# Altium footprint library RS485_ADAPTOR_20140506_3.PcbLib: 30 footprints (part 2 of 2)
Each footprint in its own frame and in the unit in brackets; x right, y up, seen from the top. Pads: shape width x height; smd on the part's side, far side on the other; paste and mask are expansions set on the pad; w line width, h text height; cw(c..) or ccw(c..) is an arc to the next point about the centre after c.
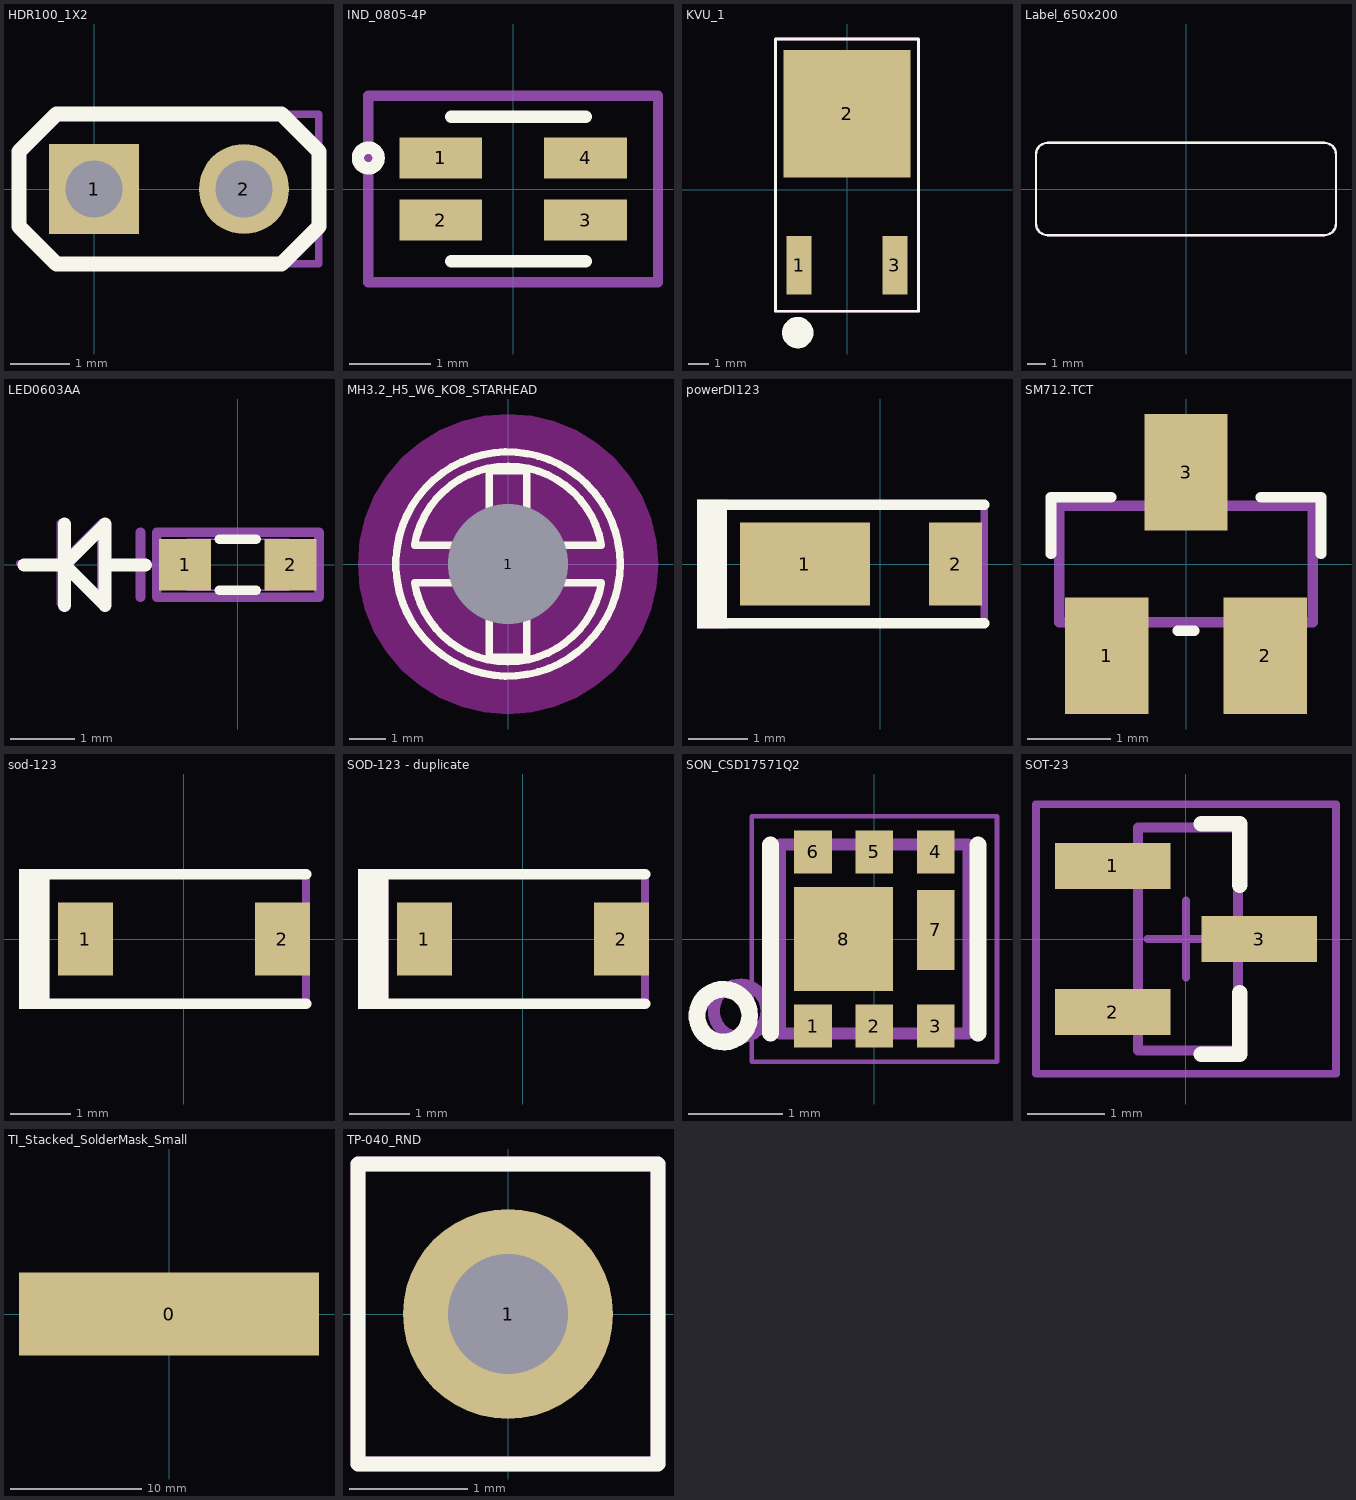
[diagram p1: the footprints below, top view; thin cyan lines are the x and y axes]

## HDR100_1X2 [mil]
height 118.11
pads (2):
  rect 60x60 hole 38: 1(0,0)
  round 60 hole 38: 2(100,0)
Top Overlay:
  lines w10: -50,-25 -50,25 -25,50 125,50 150,25 150,-25 125,-50 -25,-50 -50,-25
Mechanical 5:
  lines w5: -50,-25 -25,-50 150,-50 150,50 -25,50 -50,25 -50,-25
  text ".Designator" at 97,-69 h30

## IND_0805-4P [mil]
height 118.11
pads (4):
  rect 40x20 smd: 1(-35,15) 2(-35,-15) 3(35,-15) 4(35,15)
Top Overlay:
  circle w6: c-70,15 r5
  lines w6: -30,-35 35,-35 ; -30,35 35,35
Mechanical 5:
  lines w5: -70,-45 -70,45 70,45 70,-45 -70,-45
  text "*" at -95,-2 h30
  text ".Designator" at -26,-14 h30

## KVU_1 [mm]
height 3
pads (3):
  rect 1.2x2.8 smd: 1(-2.29,-3.635) 3(2.29,-3.635)
  rect 6.096x6.096 smd: 2(0,3.635)
Top Overlay:
  circle w0.889: c-2.362,-6.858 r0.305
  lines w0.127: -3.429,-5.841 -3.429,7.216 3.429,7.216 3.429,-5.841 -3.429,-5.841
Mechanical 5:
  lines w0.127: -3.429,-5.841 3.429,-5.841 3.429,7.216 -3.429,7.216 -3.429,-5.841
  text ".Designator" at -0.254,1.422 h0.76

## Label_650x200 [mil] "Thermal Transfer Label"
height 1
pads (1):
  round 1 on Mech13: 0(0,0)
Top Overlay:
  lines w5: -325,-75 ccw(c-300,-75) -300,-100 300,-100 ccw(c300,-75) 325,-75 325,75 ccw(c300,75) 300,100 -300,100 ccw(c-300,75) -325,75 -325,-75
Mechanical 5:
  lines w5: -325,-75 ccw(c-300,-75) -300,-100 300,-100 ccw(c300,-75) 325,-75 325,75 ccw(c300,75) 300,100 -300,100 ccw(c-300,75) -325,75 -325,-75
  text ".Designator" at -60,-20 h30
3D body: height 1, standoff 0, extent -325.51,-100.51 325.51,100.51

## LED0603AA [mil]
height 118.11
pads (2):
  rect 32x32 smd: 1(-32.48,0) 2(32.48,0)
Top Overlay:
  lines w6: -11.42,-15.75 11.42,-15.75 ; -11.42,15.75 11.42,15.75
  lines w8: -131.79,-0.04 -106.79,-0.04 ; -106.79,-25.04 -106.79,24.96 ; -81.79,-0.04 -56.79,-0.04 ; -106.79,-0.04 -81.79,-25.04 -81.79,24.96 -106.79,-0.04
  text ".designator" at -55,40 h40
Mechanical 5:
  lines w6: -60,-20 -60,20 ; -50,-20 -50,20 50,20 50,-20 -50,-20
  text ".designator" at -55,40 h30
Mechanical 15:
  lines w1: -31.5,-15.75 -31.5,15.75 31.5,15.75 31.5,-15.75 -31.5,-15.75
  lines w3.94: -134.79,0.96 -109.79,0.96 ; -109.79,-24.04 -109.79,25.96 ; -84.79,0.96 -59.79,0.96 ; -109.79,0.96 -84.79,-24.04 -84.79,25.96 -109.79,0.96

## MH3.2_H5_W6_KO8_STARHEAD [mil]
height 118.11
pads (1):
  round 20 / inner round 142 / far side round 20 hole 128 unplated mask+64: 1(0,0)
Top Overlay:
  circle w8: c0,0 r120
  lines w8: -100,-20 -20,-20 -20,-100 20,-100 20,-20 100,-20 ; -100.02,-19.91 ccw(c0,-3.35) 99.99,-20.08 ; -100,20 -20,20 -20,100 20,100 20,20 100,20 ; -99.99,20.09 cw(c0,3.36) 100.02,19.92
Keep-Out Layer:
  region: 160.49,0 158.52,25.11 152.64,49.6 143,72.86 129.84,94.34 113.49,113.49 94.34,129.84 72.86,143 49.6,152.64 25.11,158.52 0,160.49 -25.11,158.52 -49.6,152.64 -72.86,143 -94.34,129.84 -113.49,113.49 -129.84,94.34 -143,72.86 -152.64,49.6 -158.52,25.11 -160.49,0 -158.52,-25.11 -152.64,-49.6 -143,-72.86 -129.84,-94.34 -113.49,-113.49 -94.34,-129.84 -72.86,-143 -49.6,-152.64 -25.11,-158.52 0,-160.49 25.11,-158.52 49.6,-152.64 72.86,-143 94.34,-129.84 113.49,-113.49 129.84,-94.34 143,-72.86 152.64,-49.6 158.52,-25.11

## powerDI123 [mm]
height 3
pads (2):
  rect 2.2x1.4 smd: 1(-1.275,0)
  rect 0.9x1.4 smd: 2(1.275,0)
Top Overlay:
  rectangle: -3.099,-1.092 -2.591,1.092
  lines w0.178: -2.946,-1.003 1.759,-1.003 ; -2.946,1.003 1.759,1.003
Mechanical 5:
  rectangle: -3.099,-1.092 -2.591,1.092
  lines w0.127: -2.946,-1.003 1.759,-1.003 1.759,1.003 -2.946,1.003
  text ".Designator" at -1.27,-0.254 h0.76
3D body: height 1, standoff 0, extent -2.375,-0.965 1.525,0.965

## SM712.TCT [mm]
height 3
pads (3):
  rect 1x1.4 smd: 1(-0.95,-1.1) 2(0.95,-1.1) 3(0,1.1)
Top Overlay:
  lines w0.127: -1.62,0.125 -1.62,0.8 -0.9,0.8 ; -0.1,-0.8 0.1,-0.8 ; 0.9,0.8 1.62,0.8 1.62,0.125
Mechanical 5:
  lines w0.127: -1.52,-0.7 1.52,-0.7 1.52,0.7 -1.52,0.7 -1.52,-0.7
  text ".Designator" at -0.95,-0.2 h0.56
3D body: height 1.08, standoff 0, extent -1.5,-1.32 1.5,1.32

## sod-123 [mm]
height 3
pads (2):
  rect 0.915x1.22 smd: 1(-1.637,0) 2(1.637,0)
Top Overlay:
  rectangle: -2.743,-1.168 -2.235,1.168
  lines w0.178: -2.413,-1.079 2.032,-1.079 ; -2.413,1.079 2.032,1.079
Mechanical 5:
  rectangle: -2.743,-1.168 -2.235,1.168
  lines w0.127: -2.413,-1.079 2.032,-1.079 2.032,1.079 -2.413,1.079
  text ".Designator" at 0.61,0.432 h0.76
3D body: height 1.35, standoff 0, extent -1.932,-0.9 1.932,0.9

## SOD-123 - duplicate [mm]
pads (2):
  rect 0.915x1.22 smd: 1(-1.637,0) 2(1.637,0)
Top Overlay:
  rectangle: -2.743,-1.168 -2.235,1.168
  lines w0.178: -2.413,-1.079 2.032,-1.079 ; -2.413,1.079 2.032,1.079
Mechanical 5:
  rectangle: -2.743,-1.168 -2.235,1.168
  lines w0.127: -2.413,-1.079 2.032,-1.079 2.032,1.079 -2.413,1.079
  text ".Designator" at 1.143,2.819 h0.76
3D body: height 1.35, standoff 0, extent -1.932,-0.9 1.932,0.9

## SON_CSD17571Q2 [mm] "SON, MOSFET, N-CH, 30V, 22A, SON 2X2 MM"
height 0.85
pads (8):
  rect 0.4x0.455 smd mask+0.038: 1(-0.65,-0.923) 2(0,-0.923) 5(0,0.923) 6(-0.65,0.923)
  rect 0.4x0.455 smd: 3(0.65,-0.923) 4(0.65,0.923)
  rect 0.4x0.85 smd mask+0.038: 7(0.65,0.096)
  rect 1.05x1.1 smd mask+0.038: 8(-0.325,0)
Top Overlay:
  circle w0.178: c-1.6,-0.813 r0.279
  lines w0.178: -1.1,-1 -1.1,1 ; 1.1,-1 1.1,1
  text ".Designator" at -1.397,0.127 h1.02
Mechanical 5:
  circle w0.127: c-1.422,-0.762 r0.279
  lines w0.127: -1,-1 1,-1 1,1 -1,1 -1,-1
  text ".Designator" at 0.381,-0.508 h0.76
Mechanical 15:
  lines w0.05: -1.3,-1.3 -1.3,1.3 1.3,1.3 1.3,-1.3 -1.3,-1.3
3D body: height 0.85, standoff 0, extent -1,-1 1,0.975

## SOT-23 [mm]
height 3
pads (3):
  rect 1.5x0.6 smd: 1(-0.95,0.95) 2(-0.95,-0.95) 3(0.95,0)
Top Overlay:
  lines w0.2: 0.2,-1.5 0.7,-1.5 0.7,-0.7 ; 0.2,1.5 0.7,1.5 0.7,0.7
Mechanical 5:
  lines w0.127: -1.16,-1.15 -1.16,-0.75 -0.625,-0.75 -0.625,0.75 -1.16,0.75 -1.16,1.15 -0.625,1.15 -0.625,1.45 0.675,1.45 0.675,0.2 1.21,0.2 1.21,-0.2 0.675,-0.2 0.675,-1.45 -0.625,-1.45 -0.625,-1.15 -1.16,-1.15
  text ".Designator" at -0.175,1.225 h0.64
Mechanical 15:
  lines w0.1: -0.5,0 0.5,0 ; 0,-0.5 0,0.5 ; -1.95,-1.75 1.95,-1.75 1.95,1.75 -1.95,1.75 -1.95,-1.75
3D body: height 1, standoff 0, extent -1.16,-1.45 1.21,1.45

## TI_Stacked_SolderMask_Small [mm]
height 3
pads (1):
  rect 22.86x6.35 smd paste-3.175 mask-3.175: 0(0,0)
Top Solder:
  drawing of 18 lines, arcs and shapes, not listed

## TP-040_RND [mil]
height 118.11
pads (1):
  round 70 / inner round 62 / far side round 62 hole 40: 1(0,0)
Top Overlay:
  lines w5: -50,-50 50,-50 50,50 -50,50 -50,-50
Mechanical 5:
  lines w5: -50,-50 -50,50 50,50 50,-50 -50,-50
